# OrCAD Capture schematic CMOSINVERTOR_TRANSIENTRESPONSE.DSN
size A
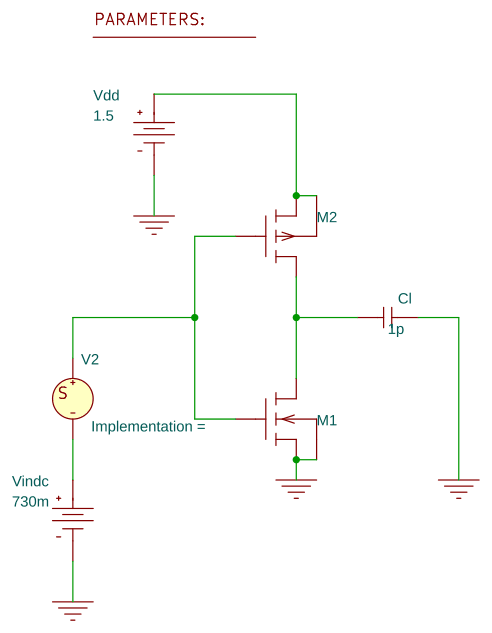
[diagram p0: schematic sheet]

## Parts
1  PARAM
Cl  1p  [RAD/CK05]
M1  MbreakN
M2  MbreakP4
V2  VSTIM
Vdd  VDC
Vindc  VDC

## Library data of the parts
1 = PARAM: Cvar: 1pF; W1: 25u; W2: 75u
Cl = C
M1 = MbreakN: AD: {3*0.35u*W1}; AS: {3*0.35u*W1}; L: 0.35u; PD: {W1+6*0.35u}; PS: {W1+6*0.35u}; W: {W1}
M2 = MbreakP4: AD: {3*0.35u*W2}; AS: {3*0.35u*W2}; L: 0.35u; PD: {W2+6*0.35u}; PS: {W2+6*0.35u}; W: {W2}
V2 = VSTIM
Vdd = VDC: DC: 1.5
Vindc = VDC: DC: 730m

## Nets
0: Cl.2 M1.0(s) M1.4(b) Vdd.1(-) Vindc.1(-)
N00319: Cl.1 M1.2(d) M2.2(d)
N00354: M2.1(s) M2.4(b) Vdd.0(+)
N00392: M1.1(g) M2.0(g) V2.0(+)
N06052: V2.1(-) Vindc.0(+)
